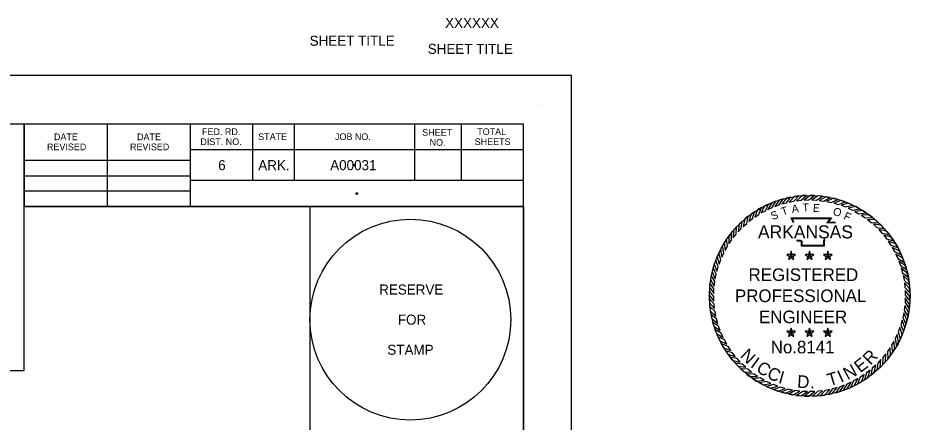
# Model space of a CAD drawing. Extents: x 0 to 19, y -0.6 to 11.3.
# Drawn here: x 13.69 to 19.02, y 8.93 to 11.34 of the extents above; entities that cross this region are included whole.
import ezdxf

# ---------------------------------------------------------------- set-up
doc = ezdxf.new("R2010")
doc.units = 0
for name, color, linetype in [('G-ANNO-STMP', 7, 'Continuous'), ('G-ANNO-TEXT', 7, 'Continuous'), ('G-Border-Paper', 7, 'Continuous'), ('G-Border-Sheet', 7, 'Continuous'), ('G-No Plot-Anchor', 7, 'Continuous'), ('G-No Plot-Border-1', 7, 'Continuous'), ('G-No Plot-Border-2', 7, 'Continuous'), ('G-No Plot-Stamp-1', 7, 'Continuous'), ('G-No Plot-Stamp-2', 7, 'Continuous'), ('G-Table-Major', 7, 'Continuous'), ('G-Table-Minor', 7, 'Continuous')]:
    doc.layers.add(name, color=color, linetype=linetype)

msp = doc.modelspace()

# ---------------------------------------------------------------- linework, layer by layer
at = {"layer": 'G-ANNO-STMP'}
for points in [[(18.2203, 10.2486), (18.1962, 10.2394), (18.1735, 10.1994), (18.1989, 10.2109)], [(18.2652, 10.2627), (18.2405, 10.2554), (18.2148, 10.2173), (18.241, 10.2268)], [(18.3112, 10.2732), (18.2859, 10.2679), (18.2573, 10.2319), (18.2842, 10.2393)], [(18.3578, 10.2801), (18.3322, 10.2768), (18.3008, 10.2431), (18.3282, 10.2484)], [(18.4048, 10.2833), (18.379, 10.282), (18.3451, 10.2509), (18.3728, 10.254)], [(18.4519, 10.2828), (18.4261, 10.2835), (18.3899, 10.2552), (18.4177, 10.2561)], [(18.4988, 10.2786), (18.4732, 10.2813), (18.4348, 10.256), (18.4627, 10.2546)], [(18.5453, 10.2707), (18.5199, 10.2755), (18.4797, 10.2532), (18.5073, 10.2497)], [(18.591, 10.2592), (18.5661, 10.266), (18.5242, 10.2469), (18.5515, 10.2412)], [(18.6356, 10.2442), (18.6113, 10.2529), (18.5681, 10.2371), (18.5949, 10.2294)], [(18.0939, 10.1859), (18.0726, 10.1714), (18.06, 10.1272), (18.082, 10.1443)], [(18.1344, 10.2101), (18.112, 10.1973), (18.0959, 10.1542), (18.1192, 10.1695)], [(18.1766, 10.2311), (18.1533, 10.22), (18.1338, 10.1783), (18.1582, 10.1918)], [(18.6789, 10.2257), (18.6554, 10.2362), (18.6111, 10.224), (18.6372, 10.2141)], [(18.7207, 10.2039), (18.698, 10.2162), (18.6529, 10.2074), (18.6781, 10.1956)], [(18.7606, 10.1788), (18.739, 10.1929), (18.6933, 10.1877), (18.7175, 10.1739)], [(18.0555, 10.1587), (18.0354, 10.1425), (18.0263, 10.0974), (18.0469, 10.1162)], [(18.7984, 10.1507), (18.778, 10.1665), (18.732, 10.1649), (18.7551, 10.1492)], [(18.8339, 10.1197), (18.8148, 10.137), (18.7688, 10.1391), (18.7906, 10.1216)], [(17.9857, 10.0955), (17.9684, 10.0764), (17.9664, 10.0304), (17.9838, 10.0522)], [(18.0194, 10.1284), (18.0006, 10.1107), (17.995, 10.0651), (18.0141, 10.0854)], [(18.8669, 10.0861), (18.8491, 10.1048), (18.8035, 10.1104), (18.8238, 10.0914)], [(18.8971, 10.0499), (18.8809, 10.07), (18.8358, 10.0792), (18.8546, 10.0586)], [(17.9547, 10.06), (17.939, 10.0396), (17.9406, 9.9936), (17.9562, 10.0167)], [(18.9244, 10.0115), (18.9098, 10.0328), (18.8656, 10.0455), (18.8827, 10.0235)], [(17.9016, 9.9823), (17.8892, 9.9596), (17.898, 9.9145), (17.9099, 9.9397)], [(17.9266, 10.0222), (17.9125, 10.0006), (17.9177, 9.9549), (17.9315, 9.9791)], [(18.9485, 9.9711), (18.9357, 9.9935), (18.8926, 10.0096), (18.9079, 9.9863)], [(17.8798, 9.9405), (17.8692, 9.917), (17.8815, 9.8727), (17.8913, 9.8987)], [(18.3122, 9.9224), (18.3061, 9.9309), (18.2861, 9.9309), (18.3023, 9.9192)], [(18.3122, 9.9224), (18.3023, 9.9192), (18.2961, 9.9003), (18.3122, 9.912)], [(18.3122, 9.9224), (18.3184, 9.9309), (18.3122, 9.9499), (18.3061, 9.9309)], [(18.3122, 9.9224), (18.3222, 9.9192), (18.3383, 9.9309), (18.3184, 9.9309)], [(18.3122, 9.9224), (18.3122, 9.912), (18.3283, 9.9003), (18.3222, 9.9192)], [(18.4219, 9.9224), (18.4158, 9.9309), (18.3958, 9.9309), (18.412, 9.9192)], [(18.4219, 9.9224), (18.412, 9.9192), (18.4058, 9.9003), (18.4219, 9.912)], [(18.4219, 9.9224), (18.4281, 9.9309), (18.4219, 9.9499), (18.4158, 9.9309)], [(18.4219, 9.9224), (18.4319, 9.9192), (18.448, 9.9309), (18.4281, 9.9309)], [(18.4219, 9.9224), (18.4219, 9.912), (18.4381, 9.9003), (18.4319, 9.9192)], [(18.5317, 9.9224), (18.5255, 9.9309), (18.5056, 9.9309), (18.5217, 9.9192)], [(18.5317, 9.9224), (18.5217, 9.9192), (18.5155, 9.9003), (18.5317, 9.912)], [(18.5317, 9.9224), (18.5378, 9.9309), (18.5317, 9.9499), (18.5255, 9.9309)], [(18.5317, 9.9224), (18.5416, 9.9192), (18.5577, 9.9309), (18.5378, 9.9309)], [(18.5317, 9.9224), (18.5317, 9.912), (18.5478, 9.9003), (18.5416, 9.9192)], [(18.9695, 9.9289), (18.9584, 9.9522), (18.9167, 9.9716), (18.9302, 9.9472)], [(18.987, 9.8852), (18.9779, 9.9093), (18.9378, 9.9319), (18.9493, 9.9065)], [(17.8613, 9.8972), (17.8526, 9.8729), (17.8683, 9.8297), (17.8761, 9.8564)], [(19.0011, 9.8402), (18.9939, 9.865), (18.9557, 9.8907), (18.9652, 9.8645)], [(17.8462, 9.8525), (17.8395, 9.8276), (17.8586, 9.7858), (17.8642, 9.8131)], [(19.0116, 9.7943), (19.0063, 9.8195), (18.9703, 9.8482), (18.9777, 9.8213)], [(17.8269, 9.7604), (17.8241, 9.7347), (17.8495, 9.6964), (17.8508, 9.7242)], [(17.8347, 9.8069), (17.83, 9.7815), (17.8523, 9.7413), (17.8558, 9.7689)], [(19.0185, 9.7477), (19.0152, 9.7733), (18.9816, 9.8046), (18.9868, 9.7772)], [(19.0217, 9.7007), (19.0204, 9.7264), (18.9893, 9.7603), (18.9924, 9.7326)], [(17.8227, 9.7135), (17.8219, 9.6877), (17.8503, 9.6514), (17.8494, 9.6793)], [(19.0212, 9.6536), (19.0219, 9.6793), (18.9936, 9.7156), (18.9945, 9.6877)], [(17.8222, 9.6664), (17.8235, 9.6406), (17.8545, 9.6067), (17.8515, 9.6344)], [(19.017, 9.6066), (19.0198, 9.6323), (18.9944, 9.6706), (18.9931, 9.6428)], [(17.8254, 9.6194), (17.8287, 9.5938), (17.8623, 9.5624), (17.8571, 9.5898)], [(19.0091, 9.5602), (19.0139, 9.5855), (18.9916, 9.6258), (18.9881, 9.5981)], [(17.8322, 9.5728), (17.8375, 9.5475), (17.8735, 9.5189), (17.8662, 9.5458)], [(18.9976, 9.5145), (19.0044, 9.5394), (18.9853, 9.5812), (18.9797, 9.5539)], [(17.8427, 9.5268), (17.85, 9.5021), (17.8881, 9.4764), (17.8787, 9.5026)], [(18.9641, 9.4265), (18.9747, 9.4501), (18.9624, 9.4944), (18.9525, 9.4683)], [(18.9826, 9.4698), (18.9913, 9.4941), (18.9755, 9.5374), (18.9678, 9.5106)], [(17.8568, 9.4819), (17.866, 9.4578), (17.906, 9.4351), (17.8946, 9.4605)], [(18.3122, 9.463), (18.3061, 9.4715), (18.2861, 9.4715), (18.3023, 9.4598)], [(18.3122, 9.463), (18.3023, 9.4598), (18.2961, 9.4408), (18.3122, 9.4525)], [(18.3122, 9.463), (18.3184, 9.4715), (18.3122, 9.4904), (18.3061, 9.4715)], [(18.3122, 9.463), (18.3222, 9.4598), (18.3383, 9.4715), (18.3184, 9.4715)], [(18.3122, 9.463), (18.3122, 9.4525), (18.3283, 9.4408), (18.3222, 9.4598)], [(18.4219, 9.463), (18.4158, 9.4715), (18.3958, 9.4715), (18.412, 9.4598)], [(18.4219, 9.463), (18.412, 9.4598), (18.4058, 9.4408), (18.4219, 9.4525)], [(18.4219, 9.463), (18.4281, 9.4715), (18.4219, 9.4904), (18.4158, 9.4715)], [(18.4219, 9.463), (18.4319, 9.4598), (18.448, 9.4715), (18.4281, 9.4715)], [(18.4219, 9.463), (18.4219, 9.4525), (18.4381, 9.4408), (18.4319, 9.4598)], [(18.5317, 9.463), (18.5255, 9.4715), (18.5056, 9.4715), (18.5217, 9.4598)], [(18.5317, 9.463), (18.5217, 9.4598), (18.5155, 9.4408), (18.5317, 9.4525)], [(18.5317, 9.463), (18.5378, 9.4715), (18.5317, 9.4904), (18.5255, 9.4715)], [(18.5317, 9.463), (18.5416, 9.4598), (18.5577, 9.4715), (18.5378, 9.4715)], [(18.5317, 9.463), (18.5317, 9.4525), (18.5478, 9.4408), (18.5416, 9.4598)], [(18.9423, 9.3848), (18.9546, 9.4074), (18.9459, 9.4526), (18.934, 9.4273)], [(17.8744, 9.4382), (17.8854, 9.4148), (17.9271, 9.3954), (17.9137, 9.4198)], [(17.8953, 9.3959), (17.9082, 9.3736), (17.9513, 9.3575), (17.9359, 9.3808)], [(18.9172, 9.3449), (18.9313, 9.3665), (18.9261, 9.4122), (18.9123, 9.3879)], [(17.9195, 9.3555), (17.9341, 9.3342), (17.9783, 9.3215), (17.9612, 9.3436)], [(18.8582, 9.2715), (18.8755, 9.2907), (18.8775, 9.3366), (18.8601, 9.3149)], [(18.8891, 9.307), (18.9049, 9.3275), (18.9033, 9.3734), (18.8876, 9.3504)], [(17.9468, 9.3171), (17.963, 9.297), (18.0081, 9.2879), (17.9893, 9.3085)], [(17.977, 9.281), (17.9947, 9.2622), (18.0404, 9.2566), (18.02, 9.2757)], [(18.8245, 9.2386), (18.8432, 9.2563), (18.8489, 9.302), (18.8298, 9.2816)], [(18.01, 9.2473), (18.0291, 9.23), (18.075, 9.228), (18.0533, 9.2454)], [(18.7499, 9.1811), (18.7712, 9.1957), (18.7839, 9.2399), (18.7619, 9.2228)], [(18.7883, 9.2084), (18.8084, 9.2246), (18.8176, 9.2696), (18.797, 9.2509)], [(18.0455, 9.2163), (18.0659, 9.2006), (18.1119, 9.2022), (18.0888, 9.2178)], [(18.0833, 9.1882), (18.1049, 9.1741), (18.1506, 9.1793), (18.1264, 9.1931)], [(18.6673, 9.136), (18.6906, 9.147), (18.71, 9.1887), (18.6856, 9.1753)], [(18.7095, 9.1569), (18.7319, 9.1698), (18.748, 9.2128), (18.7247, 9.1975)], [(18.1232, 9.1632), (18.1458, 9.1508), (18.191, 9.1596), (18.1657, 9.1714)], [(18.1649, 9.1413), (18.1885, 9.1308), (18.2328, 9.1431), (18.2067, 9.1529)], [(18.2083, 9.1228), (18.2326, 9.1142), (18.2758, 9.1299), (18.249, 9.1377)], [(18.2529, 9.1078), (18.2778, 9.1011), (18.3197, 9.1201), (18.2924, 9.1258)], [(18.4861, 9.0869), (18.5117, 9.0903), (18.543, 9.1239), (18.5157, 9.1187)], [(18.5327, 9.0938), (18.5579, 9.0991), (18.5866, 9.1351), (18.5597, 9.1278)], [(18.5786, 9.1043), (18.6034, 9.1116), (18.6291, 9.1497), (18.6029, 9.1403)], [(18.6236, 9.1184), (18.6477, 9.1276), (18.6703, 9.1676), (18.6449, 9.1561)], [(18.2986, 9.0963), (18.324, 9.0916), (18.3642, 9.1139), (18.3365, 9.1173)], [(18.345, 9.0885), (18.3707, 9.0857), (18.4091, 9.1111), (18.3812, 9.1124)], [(18.392, 9.0843), (18.4178, 9.0835), (18.454, 9.1118), (18.4261, 9.1109)], [(18.4391, 9.0837), (18.4649, 9.085), (18.4988, 9.1161), (18.4711, 9.113)]]:
    msp.add_lwpolyline(points, close=True, dxfattribs=at)
for points in [[(18.3258, 10.119), (18.3118, 10.1493), (18.5538, 10.1494), (18.5336, 10.124), (18.5501, 10.1242), (18.5638, 10.1244), (18.5775, 10.1229)], [(18.3293, 10.1206), (18.3178, 10.1455), (18.5459, 10.1456), (18.5256, 10.1201), (18.5501, 10.1204), (18.5636, 10.1206), (18.5771, 10.1191)], [(18.5157, 10.0176), (18.5116, 10.0142), (18.5102, 10.0092), (18.5088, 9.9966), (18.5088, 9.9799), (18.3737, 9.9799), (18.3737, 10.0025), (18.3737, 10.0075), (18.3683, 10.0092), (18.349, 10.0092), (18.3456, 10.0144)], [(18.5133, 10.0205), (18.5082, 10.0164), (18.5064, 10.0099), (18.505, 9.9969), (18.505, 9.9838), (18.3776, 9.9838), (18.3776, 10.0025), (18.3776, 10.0104), (18.3688, 10.013), (18.3511, 10.013), (18.3488, 10.0165)]]:
    msp.add_lwpolyline(points, dxfattribs=at)
at = {"layer": 'G-ANNO-TEXT'}
msp.add_line((16.821, 10.8269), (16.821, 10.8269), dxfattribs=at)
at = {"layer": 'G-Border-Paper'}
msp.add_lwpolyline([(17, 11), (0, 11), (0, 0), (17, 0)], close=True, dxfattribs=at)
at = {"layer": 'G-Border-Sheet'}
for p in [(0.758, 10.7116), (16.7116, 0.2884)]:
    msp.add_line(p, (16.7116, 10.7116), dxfattribs=at)
at = {"layer": 'G-No Plot-Anchor'}
for centre in [(15.7013, 10.4639), (15.7161, 10.2941)]:
    msp.add_circle(centre, 0.005, dxfattribs=at)
at = {"layer": 'G-No Plot-Border-1'}
msp.add_lwpolyline([(0.758, 0.2884), (0.758, 10.7116), (13.7281, 10.7116), (13.7281, 10.2161), (15.4366, 10.2161), (15.4366, 8.7411), (16.7116, 8.7411), (16.7116, 0.2884)], close=True, dxfattribs=at)
at = {"layer": 'G-No Plot-Border-2'}
msp.add_lwpolyline([(0.758, 0.2884), (0.758, 10.7116), (12.3781, 10.7116), (12.3781, 9.2366), (13.7281, 9.2366), (13.7281, 10.2161), (14.7206, 10.2161), (16.7116, 10.2161), (16.7116, 0.2884)], close=True, dxfattribs=at)
at = {"layer": 'G-No Plot-Stamp-1'}
for centre in [(18.4233, 9.6835), (16.0366, 9.5411)]:
    msp.add_circle(centre, 0.6, dxfattribs=at)
at = {"layer": 'G-No Plot-Stamp-2'}
msp.add_circle((18.4233, 9.6835), 0.6, dxfattribs=at)
at = {"layer": 'G-Table-Major'}
for p, q in [((13.7281, 10.2168), (13.7281, 10.7116)), ((14.7206, 10.7116), (14.7206, 10.2161)), ((13.7281, 10.4946), (14.7206, 10.4946)), ((16.7116, 10.2161), (13.7281, 10.2161))]:
    msp.add_line(p, q, dxfattribs=at)
at = {"layer": 'G-Table-Minor'}
for p, q in [((14.2256, 10.2165), (14.2256, 10.7116)), ((15.0926, 10.7116), (15.0926, 10.3716)), ((15.3411, 10.7116), (15.3411, 10.3716)), ((16.0616, 10.7116), (16.0616, 10.3716)), ((16.3396, 10.7116), (16.3396, 10.3716)), ((16.7116, 10.5656), (16.7116, 10.5656)), ((16.7116, 10.5561), (14.7206, 10.5561)), ((13.7281, 10.4011), (14.7206, 10.4011)), ((16.7116, 10.3716), (14.7206, 10.3716)), ((13.7281, 10.3096), (14.7206, 10.3096))]:
    msp.add_line(p, q, dxfattribs=at)

# ---------------------------------------------------------------- texts
at = {"layer": 'G-ANNO-STMP'}
for s, height, rotation, p in [('S', 0.0477, 19.7726, (18.1998, 10.1349)), ('T', 0.0477, 16.9015, (18.2605, 10.1621)), ('A', 0.0477, 8.6788, (18.3184, 10.1773)), ('T', 0.0477, 1.4789, (18.3801, 10.1868)), ('E', 0.0477, 356.672, (18.4412, 10.1853)), ('O', 0.0477, 341.2218, (18.5571, 10.1689)), ('F', 0.0477, 335.3628, (18.6214, 10.1438)), ('N', 0.0754, 315.2676, (18.0028, 9.3216)), ('R', 0.0754, 45.478, (18.7853, 9.2657)), ('I', 0.0754, 324.2141, (18.0641, 9.2609)), ('C', 0.0754, 328.6873, (18.0982, 9.2342)), ('E', 0.0754, 37.6498, (18.725, 9.2201)), ('C', 0.0754, 336.5155, (18.1624, 9.1943)), ('I', 0.0754, 344.3437, (18.2314, 9.1635)), ('T', 0.0754, 16.7747, (18.54, 9.1425)), ('I', 0.0754, 24.2301, (18.6092, 9.1624)), ('N', 0.0754, 28.7033, (18.6493, 9.1786)), ('D', 0.0754, 356.6451, (18.3466, 9.1349)), ('.', 0.0754, 4.846, (18.4256, 9.1298))]:
    msp.add_text(s, height=height, rotation=rotation, dxfattribs=at).set_placement(p)
for s, height, p in [('ARKANSAS', 0.07791, (18.114, 10.0263)), ('REGISTERED', 0.07543, (18.0574, 9.7719)), ('PROFESSIONAL', 0.07543, (17.9765, 9.6458)), ('ENGINEER', 0.07543, (18.1202, 9.5197)), ('No.8141', 0.07513, (18.1905, 9.3398))]:
    msp.add_text(s, height=height, dxfattribs=at).set_placement(p)
at = {"layer": 'G-ANNO-TEXT'}
for s, height, p in [('XXXXXX', 0.06, (16.2442, 11.2838)), ('SHEET TITLE', 0.06, (15.4345, 11.1771)), ('SHEET TITLE', 0.06, (16.1404, 11.1286)), ('FED. RD.', 0.04, (14.7913, 10.6439)), ('SHEET', 0.04, (16.1072, 10.6396)), ('TOTAL', 0.04, (16.4361, 10.6439)), ('DATE', 0.04, (13.9066, 10.6131)), ('DATE', 0.04, (14.4029, 10.6131)), ('DIST. NO.', 0.04, (14.7816, 10.5839)), ('STATE', 0.04, (15.1271, 10.6139)), ('JOB NO.', 0.04, (15.5861, 10.6139)), ('NO.', 0.04, (16.1515, 10.5796)), ('SHEETS', 0.04, (16.421, 10.5839)), ('REVISED', 0.04, (13.8646, 10.5531)), ('REVISED', 0.04, (14.3608, 10.5531)), ('6', 0.06, (14.8879, 10.4339)), ('ARK.', 0.06, (15.1276, 10.4339)), ('A00031', 0.06, (15.5573, 10.4339))]:
    msp.add_text(s, height=height, dxfattribs=at).set_placement(p)
at = {"layer": 'G-No Plot-Stamp-1'}
for s, p in [('RESERVE', (15.85, 9.6911)), ('FOR ', (15.9617, 9.5111)), ('STAMP', (15.8989, 9.3311))]:
    msp.add_text(s, height=0.06, dxfattribs=at).set_placement(p)

doc.saveas('drawing.dxf')
